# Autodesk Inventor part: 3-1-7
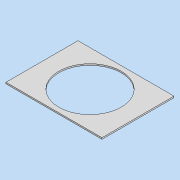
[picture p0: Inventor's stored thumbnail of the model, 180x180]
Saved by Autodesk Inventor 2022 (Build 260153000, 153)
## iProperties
Created: 2021-07
Part Number: 3-1-7
Material: 一般
Document SubType Name: Modeling
Designer: DesignLab
Density: 1 g/cm^3
Appearance: 既定
Author: DesignLab
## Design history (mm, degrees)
sketch "スケッチ1"
  geometry: L1 (0, 0)-(-200, 0); L2 (-200, 0)-(-200, -150); L3 (-200, -150)-(0, -150); L4 (0, -150)-(0, 0)
  constraints: 8 end point, 2 parallel, 1 horizontal, 1 perpendicular
  dimensions: "d0" = 200 distance of L3.end L2.end; "d1" = 150 distance of L2.end L1.end
extrude "押し出し1" new body sketch "スケッチ1" distance "d2" = 3; taper "d3" = 0 deg
sketch "スケッチ2"
  geometry: L1 (200, 150)-(0, 150) reference; L2 (0, 150)-(0, 0) reference; C1 r 65 at (100, 75); 2 further points
  constraints: 2 midpoint, 1 centre point
  dimensions: "d4" = 130 diameter of C1
extrude "押し出し2" cut sketch "スケッチ2" distance "d7" = 3; taper "d8" = 0 deg
node "ソリッド1"
